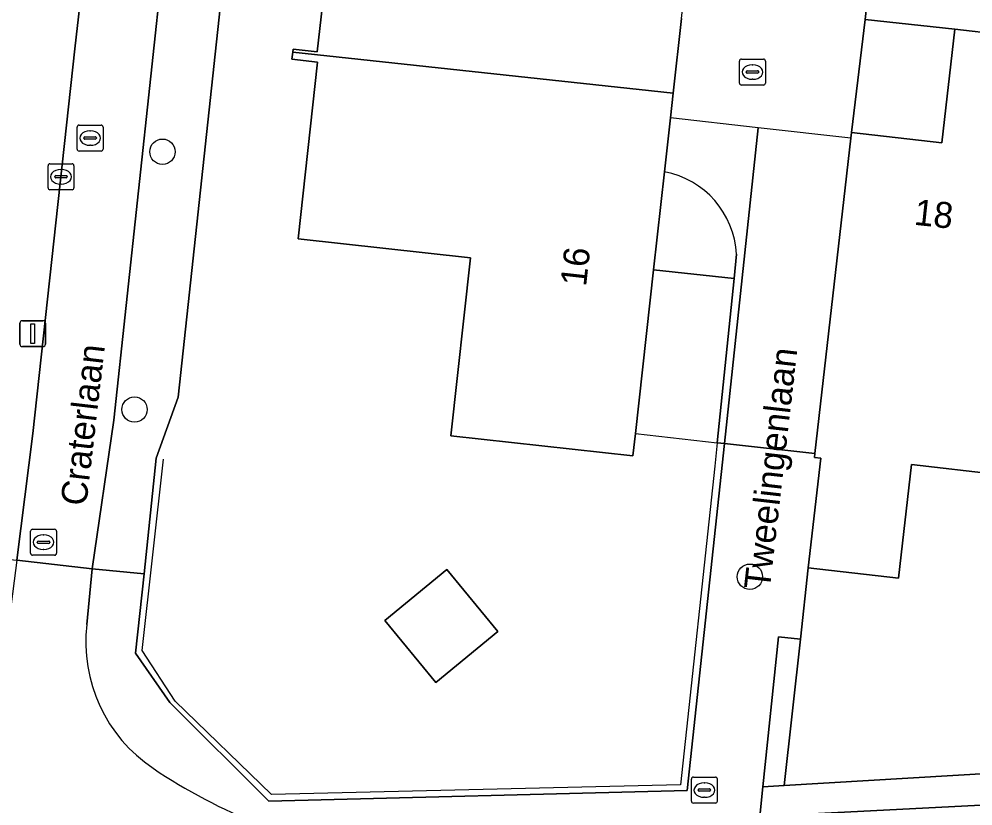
# Model space of a CAD drawing. Extents: x 162396 to 163643, y 386452 to 387406.
# Drawn here: x 162646 to 162682.82, y 386467.41 to 386497.76 of the extents above; entities that cross this region are included whole.
import ezdxf

# ---------------------------------------------------------------- set-up
doc = ezdxf.new("R2010")
doc.units = 0
for name, color, linetype in [('IMGEO_Berm_groen', 7, 'Continuous'), ('IMGEO_Boom', 7, 'Continuous'), ('IMGEO_Erf', 7, 'Continuous'), ('IMGEO_Fietspad_gesloten', 7, 'Continuous'), ('IMGEO_Fietspad_open', 7, 'Continuous'), ('IMGEO_Groenvoorziening', 7, 'Continuous'), ('IMGEO_Kolk', 7, 'Continuous'), ('IMGEO_Lichtmast', 7, 'Continuous'), ('IMGEO_Muur', 7, 'Continuous'), ('IMGEO_Openbare_ruimte_label', 7, 'Continuous'), ('IMGEO_Pand', 7, 'Continuous'), ('IMGEO_Pand_nummerreeks', 7, 'Continuous'), ('IMGEO_Pand_overbouw', 7, 'Continuous'), ('IMGEO_Rijbaan_lokaal_open', 7, 'Continuous'), ('IMGEO_Rioolput', 7, 'Continuous'), ('IMGEO_Voetpad_open', 7, 'Continuous')]:
    doc.layers.add(name, color=color, linetype=linetype)

msp = doc.modelspace()

# ---------------------------------------------------------------- linework, layer by layer
at = {"layer": 'IMGEO_Berm_groen'}
msp.add_lwpolyline([(162685.297, 386468.773), (162675.534, 386468.191), (162674.712, 386468.15), (162674.593, 386466.997), (162685.391, 386467.551)], close=True, dxfattribs=at)
at = {"layer": 'IMGEO_Boom'}
for centre in [(162651.534, 386492.646), (162650.454, 386482.699), (162674.209, 386476.249)]:
    msp.add_circle(centre, 0.489, dxfattribs=at)
at = {"layer": 'IMGEO_Erf'}
for points in [[(162653.954, 386500), (162652.14, 386483.177), (162651.294, 386480.824), (162650.821, 386476.366), (162650.496, 386473.305), (162651.817, 386471.397), (162655.639, 386467.593), (162671.786, 386468.002), (162673.225, 386481.39), (162672.948, 386481.421), (162673.598, 386487.762), (162670.493, 386488.084), (162669.791, 386481.774), (162669.695, 386480.909), (162662.664, 386481.69), (162663.427, 386488.55), (162656.767, 386489.29), (162657.524, 386496.103), (162656.532, 386496.213), (162656.562, 386496.484), (162656.576, 386496.61), (162657.511, 386496.506), (162657.899, 386500)], [(162708.804, 386484.322), (162705.271, 386484.727), (162702.148, 386485.085), (162701.66, 386480.83), (162698.283, 386481.217), (162697.979, 386478.568), (162697.474, 386478.626), (162690.7, 386479.402), (162683.78, 386480.194), (162680.447, 386480.576), (162679.946, 386476.199), (162676.46, 386476.598), (162676.157, 386473.844), (162675.534, 386468.191), (162685.297, 386468.773), (162686.376, 386468.838), (162699.459, 386469.63), (162700.524, 386469.694), (162706.572, 386470.062), (162707.634, 386470.126), (162713.9, 386470.497), (162714.941, 386470.557), (162732.655, 386471.574)]]:
    msp.add_lwpolyline(points, dxfattribs=at)
for points in [[(162678.137, 386493.391), (162681.623, 386492.992), (162682.125, 386497.376), (162678.661, 386497.746)], [(162662.512, 386476.528), (162664.477, 386474.131), (162662.08, 386472.165), (162660.114, 386474.563)]]:
    msp.add_lwpolyline(points, close=True, dxfattribs=at)
at = {"layer": 'IMGEO_Fietspad_gesloten'}
for points in [[(162648.608, 386474.401), (162648.825, 386476.553), (162645.908, 386476.892), (162645.639, 386474.787)], [(162745.417, 386471.64), (162744.381, 386471.562), (162715.01, 386469.312), (162713.97, 386469.239), (162707.758, 386468.81), (162706.663, 386468.77), (162700.617, 386468.394), (162699.554, 386468.328), (162686.477, 386467.606), (162685.391, 386467.551), (162674.593, 386466.997), (162655.671, 386466.609), (162655.276, 386466.693)]]:
    msp.add_lwpolyline(points, dxfattribs=at)
for centre, radius, start, end in [((162654.434, 386473.733), 5.864, 173.4629, 236.1556), ((162663.327, 386486.908), 21.759, 236.0268, 248.2838)]:
    msp.add_arc(centre, radius, start, end, dxfattribs=at)
at = {"layer": 'IMGEO_Fietspad_open'}
msp.add_lwpolyline([(162645.908, 386476.892), (162648.825, 386476.553), (162649.657, 386482.292), (162651.56, 386500), (162655.899, 386540.406), (162655.811, 386540.036), (162655.55, 386539.18), (162655.214, 386538.352), (162654.805, 386537.557), (162654.327, 386536.802), (162653.783, 386536.092), (162652.314, 386534.776), (162651.092, 386522.672), (162648.531, 386500), (162648.149, 386496.622), (162646.532, 386481.777)], close=True, dxfattribs=at)
at = {"layer": 'IMGEO_Groenvoorziening'}
msp.add_lwpolyline([(162676.157, 386473.844), (162675.31, 386473.932), (162674.712, 386468.15), (162675.534, 386468.191)], close=True, dxfattribs=at)
at = {"layer": 'IMGEO_Kolk'}
for p, q in [((162673.807, 386495.295), (162673.807, 386496.147)), ((162673.882, 386496.221), (162674.734, 386496.221)), ((162674.295, 386496.001), (162674.32, 386496.001)), ((162674.808, 386496.147), (162674.808, 386495.295)), ((162674.066, 386495.715), (162674.066, 386495.727)), ((162674.504, 386495.678), (162674.106, 386495.678)), ((162674.109, 386495.764), (162674.507, 386495.764)), ((162674.55, 386495.727), (162674.55, 386495.715)), ((162674.734, 386495.221), (162673.882, 386495.221)), ((162674.318, 386495.441), (162674.293, 386495.441)), ((162647.116, 386491.255), (162647.116, 386492.107)), ((162647.191, 386492.181), (162648.043, 386492.181)), ((162647.604, 386491.961), (162647.629, 386491.961)), ((162648.117, 386492.107), (162648.117, 386491.255)), ((162647.375, 386491.675), (162647.375, 386491.687)), ((162647.813, 386491.638), (162647.415, 386491.638)), ((162647.418, 386491.724), (162647.816, 386491.724)), ((162647.859, 386491.687), (162647.859, 386491.675)), ((162648.043, 386491.181), (162647.191, 386491.181)), ((162647.627, 386491.401), (162647.602, 386491.401))]:
    msp.add_line(p, q, dxfattribs=at)
for points in [[(162673.807, 386495.295), (162673.807, 386496.147)], [(162673.882, 386496.221), (162674.734, 386496.221)], [(162674.808, 386496.147), (162674.808, 386495.295)], [(162674.734, 386495.221), (162673.882, 386495.221)], [(162647.116, 386491.255), (162647.116, 386492.107)], [(162647.191, 386492.181), (162648.043, 386492.181)], [(162648.117, 386492.107), (162648.117, 386491.255)], [(162648.043, 386491.181), (162647.191, 386491.181)]]:
    msp.add_lwpolyline(points, dxfattribs=at)
for centre, radius, start, end in [((162673.884, 386496.145), 0.0765, 91.552, 178.448), ((162673.884, 386496.145), 0.0765, 91.552, 178.448), ((162674.732, 386496.145), 0.0765, 1.552, 88.448), ((162674.732, 386496.145), 0.0765, 1.552, 88.448), ((162674.106, 386495.724), 0.0403, 85.8775, 175.7526), ((162674.103, 386495.714), 0.0366, 178.938, 274.7102), ((162674.507, 386495.721), 0.043, 264.8664, 352.4533), ((162674.511, 386495.726), 0.0386, 1.7309, 96.639), ((162673.884, 386495.297), 0.0765, 181.552, 268.448), ((162673.884, 386495.297), 0.0765, 181.552, 268.448), ((162674.732, 386495.297), 0.0765, 271.552, 358.448), ((162674.732, 386495.297), 0.0765, 271.552, 358.448), ((162647.193, 386492.105), 0.0765, 91.552, 178.448), ((162647.193, 386492.105), 0.0765, 91.552, 178.448), ((162648.041, 386492.105), 0.0765, 1.552, 88.448), ((162648.041, 386492.105), 0.0765, 1.552, 88.448), ((162647.415, 386491.684), 0.0403, 85.8775, 175.7526), ((162647.412, 386491.674), 0.0366, 178.938, 274.7102), ((162647.816, 386491.681), 0.043, 264.8664, 352.4533), ((162647.82, 386491.686), 0.0386, 1.7309, 96.639), ((162647.193, 386491.257), 0.0765, 181.552, 268.448), ((162647.193, 386491.257), 0.0765, 181.552, 268.448), ((162648.041, 386491.257), 0.0765, 271.552, 358.448), ((162648.041, 386491.257), 0.0765, 271.552, 358.448)]:
    msp.add_arc(centre, radius, start, end, dxfattribs=at)
for centre, major_axis, ratio, start_param, end_param in [((162674.294, 386495.721), (-0.387, 0.002), 0.722429, 4.712389, 7.853982), ((162674.319, 386495.721), (-0.39, 0.002), 0.717154, 1.570796, 4.712389), ((162647.603, 386491.681), (-0.387, 0.002), 0.722429, 4.712389, 7.853982), ((162647.628, 386491.681), (-0.39, 0.002), 0.717154, 1.570796, 4.712389)]:
    msp.add_ellipse(centre, major_axis=major_axis, ratio=ratio, start_param=start_param, end_param=end_param, dxfattribs=at)
at = {"layer": 'IMGEO_Lichtmast'}
for p, q in [((162646.028, 386485.228), (162646.028, 386486.028)), ((162646.028, 386486.028), (162646.028, 386485.228)), ((162646.128, 386486.128), (162646.918, 386486.128)), ((162646.918, 386486.128), (162646.128, 386486.128)), ((162647.018, 386486.028), (162647.018, 386485.228)), ((162647.018, 386485.228), (162647.018, 386486.028)), ((162646.918, 386485.128), (162646.128, 386485.128)), ((162646.128, 386485.128), (162646.918, 386485.128))]:
    msp.add_line(p, q, dxfattribs=at)
msp.add_lwpolyline([(162646.448, 386486.003), (162646.598, 386486.003), (162646.598, 386485.253), (162646.448, 386485.253), (162646.448, 386486.003)], dxfattribs=at)
for centre, start, end in [((162646.128, 386486.028), 90, 180), ((162646.128, 386486.028), 90, 180), ((162646.918, 386486.028), 0, 90), ((162646.918, 386486.028), 360, 90), ((162646.128, 386485.228), 180, 270), ((162646.128, 386485.228), 180, 270), ((162646.918, 386485.228), 270, 0), ((162646.918, 386485.228), 270, 0)]:
    msp.add_arc(centre, 0.1, start, end, dxfattribs=at)
at = {"layer": 'IMGEO_Muur'}
for points in [[(162672.948, 386481.421), (162672.85, 386480.517)], [(162672.85, 386480.517), (162671.524, 386468.223), (162655.736, 386467.848), (162652.022, 386471.451), (162650.749, 386473.407), (162651.57, 386480.789)], [(162676.157, 386473.844), (162676.46, 386476.598)], [(162685.297, 386468.773), (162675.534, 386468.191), (162676.157, 386473.844)]]:
    msp.add_lwpolyline(points, dxfattribs=at)
at = {"layer": 'IMGEO_Pand'}
for points in [[(162671.817, 386500), (162672.462, 386505.808), (162672.793, 386508.782), (162665.724, 386509.568), (162664.964, 386502.729), (162658.285, 386503.471), (162657.899, 386500), (162657.511, 386496.506), (162656.576, 386496.61), (162656.562, 386496.484), (162671.251, 386494.908), (162671.571, 386497.786)], [(162676.46, 386476.598), (162679.946, 386476.199), (162680.447, 386480.576), (162683.78, 386480.194), (162685.702, 386496.966), (162682.125, 386497.376), (162681.623, 386492.992), (162678.137, 386493.391), (162678.111, 386493.167), (162676.718, 386481), (162676.701, 386480.849), (162676.944, 386480.821)], [(162670.914, 386491.872), (162671.145, 386493.953), (162671.251, 386494.908), (162656.562, 386496.484), (162656.532, 386496.213), (162657.524, 386496.103), (162656.767, 386489.29), (162663.427, 386488.55), (162662.664, 386481.69), (162669.695, 386480.909), (162669.791, 386481.774), (162670.493, 386488.084)], [(162662.512, 386476.528), (162660.114, 386474.563), (162662.08, 386472.165), (162664.477, 386474.131)]]:
    msp.add_lwpolyline(points, close=True, dxfattribs=at)
at = {"layer": 'IMGEO_Pand_overbouw'}
for points in [[(162674.534, 386493.571), (162671.145, 386493.953), (162670.914, 386491.872), (162670.493, 386488.084), (162669.791, 386481.774), (162672.948, 386481.421), (162673.225, 386481.39)], [(162674.534, 386493.571), (162673.225, 386481.39), (162676.718, 386481), (162678.111, 386493.167)]]:
    msp.add_lwpolyline(points, close=True, dxfattribs=at)
at = {"layer": 'IMGEO_Rijbaan_lokaal_open'}
for points in [[(162694.231, 386503.125), (162693.199, 386503.277), (162686.483, 386504.043), (162679.454, 386504.83), (162678.661, 386497.746), (162682.125, 386497.376), (162685.702, 386496.966), (162689.278, 386496.557), (162695.978, 386495.954), (162699.359, 386495.567), (162699.661, 386498.206), (162703.573, 386497.758), (162706.733, 386497.396), (162713.711, 386496.597), (162714.057, 386500), (162714.825, 386507.563)], [(162673.689, 386488.692), (162673.598, 386487.762), (162672.948, 386481.421), (162673.225, 386481.39), (162676.718, 386481), (162678.111, 386493.167), (162678.137, 386493.391), (162678.661, 386497.746), (162679.454, 386504.83)], [(162671.571, 386497.786), (162671.251, 386494.908), (162671.145, 386493.953), (162670.914, 386491.872)]]:
    msp.add_lwpolyline(points, dxfattribs=at)
msp.add_arc((162670.277, 386488.515), 3.417, 2.9638, 79.2548, dxfattribs=at)
at = {"layer": 'IMGEO_Rioolput'}
for p, q in [((162648.238, 386492.748), (162648.238, 386493.6)), ((162648.313, 386493.674), (162649.165, 386493.674)), ((162648.726, 386493.454), (162648.751, 386493.454)), ((162649.239, 386493.6), (162649.239, 386492.748)), ((162648.497, 386493.168), (162648.497, 386493.18)), ((162648.935, 386493.131), (162648.537, 386493.131)), ((162648.54, 386493.217), (162648.938, 386493.217)), ((162648.981, 386493.18), (162648.981, 386493.168)), ((162649.165, 386492.674), (162648.313, 386492.674)), ((162648.749, 386492.894), (162648.724, 386492.894)), ((162646.442, 386477.155), (162646.442, 386478.007)), ((162646.517, 386478.081), (162647.369, 386478.081)), ((162647.443, 386478.007), (162647.443, 386477.155)), ((162646.701, 386477.575), (162646.701, 386477.587)), ((162647.139, 386477.538), (162646.741, 386477.538)), ((162646.744, 386477.624), (162647.142, 386477.624)), ((162646.93, 386477.861), (162646.955, 386477.861)), ((162647.185, 386477.587), (162647.185, 386477.575)), ((162646.953, 386477.301), (162646.928, 386477.301)), ((162647.369, 386477.081), (162646.517, 386477.081)), ((162671.951, 386467.593), (162671.951, 386468.445)), ((162672.026, 386468.519), (162672.878, 386468.519)), ((162672.952, 386468.445), (162672.952, 386467.593)), ((162672.21, 386468.013), (162672.21, 386468.025)), ((162672.648, 386467.976), (162672.25, 386467.976)), ((162672.253, 386468.062), (162672.651, 386468.062)), ((162672.439, 386468.299), (162672.464, 386468.299)), ((162672.694, 386468.025), (162672.694, 386468.013)), ((162672.462, 386467.739), (162672.437, 386467.739)), ((162672.878, 386467.519), (162672.026, 386467.519))]:
    msp.add_line(p, q, dxfattribs=at)
for points in [[(162648.238, 386492.748), (162648.238, 386493.6)], [(162648.313, 386493.674), (162649.165, 386493.674)], [(162649.239, 386493.6), (162649.239, 386492.748)], [(162649.165, 386492.674), (162648.313, 386492.674)], [(162646.442, 386477.155), (162646.442, 386478.007)], [(162646.517, 386478.081), (162647.369, 386478.081)], [(162647.443, 386478.007), (162647.443, 386477.155)], [(162647.369, 386477.081), (162646.517, 386477.081)], [(162671.951, 386467.593), (162671.951, 386468.445)], [(162672.026, 386468.519), (162672.878, 386468.519)], [(162672.952, 386468.445), (162672.952, 386467.593)], [(162672.878, 386467.519), (162672.026, 386467.519)]]:
    msp.add_lwpolyline(points, dxfattribs=at)
for centre, radius, start, end in [((162648.315, 386493.598), 0.0765, 91.552, 178.448), ((162648.315, 386493.598), 0.0765, 91.552, 178.448), ((162649.163, 386493.598), 0.0765, 1.552, 88.448), ((162649.163, 386493.598), 0.0765, 1.552, 88.448), ((162648.537, 386493.177), 0.0403, 85.8775, 175.7526), ((162648.534, 386493.167), 0.0366, 178.938, 274.7102), ((162648.938, 386493.174), 0.043, 264.8664, 352.4533), ((162648.942, 386493.179), 0.0386, 1.7309, 96.639), ((162648.315, 386492.75), 0.0765, 181.552, 268.448), ((162648.315, 386492.75), 0.0765, 181.552, 268.448), ((162649.163, 386492.75), 0.0765, 271.552, 358.448), ((162649.163, 386492.75), 0.0765, 271.552, 358.448), ((162646.519, 386478.005), 0.0765, 91.552, 178.448), ((162646.519, 386478.005), 0.0765, 91.552, 178.448), ((162647.367, 386478.005), 0.0765, 1.552, 88.448), ((162647.367, 386478.005), 0.0765, 1.552, 88.448), ((162646.741, 386477.584), 0.0403, 85.8775, 175.7526), ((162646.738, 386477.574), 0.0366, 178.938, 274.7102), ((162647.142, 386477.581), 0.043, 264.8664, 352.4533), ((162647.146, 386477.586), 0.0386, 1.7309, 96.639), ((162646.519, 386477.157), 0.0765, 181.552, 268.448), ((162646.519, 386477.157), 0.0765, 181.552, 268.448), ((162647.367, 386477.157), 0.0765, 271.552, 358.448), ((162647.367, 386477.157), 0.0765, 271.552, 358.448), ((162672.028, 386468.443), 0.0765, 91.552, 178.448), ((162672.028, 386468.443), 0.0765, 91.552, 178.448), ((162672.876, 386468.443), 0.0765, 1.552, 88.448), ((162672.876, 386468.443), 0.0765, 1.552, 88.448), ((162672.25, 386468.022), 0.0403, 85.8775, 175.7526), ((162672.247, 386468.012), 0.0366, 178.938, 274.7102), ((162672.651, 386468.019), 0.043, 264.8664, 352.4533), ((162672.655, 386468.024), 0.0386, 1.7309, 96.639), ((162672.028, 386467.595), 0.0765, 181.552, 268.448), ((162672.028, 386467.595), 0.0765, 181.552, 268.448), ((162672.876, 386467.595), 0.0765, 271.552, 358.448), ((162672.876, 386467.595), 0.0765, 271.552, 358.448)]:
    msp.add_arc(centre, radius, start, end, dxfattribs=at)
for centre, major_axis, ratio, start_param, end_param in [((162648.725, 386493.174), (-0.387, 0.002), 0.722429, 4.712389, 7.853982), ((162648.75, 386493.174), (-0.39, 0.002), 0.717154, 1.570796, 4.712389), ((162646.929, 386477.581), (-0.387, 0.002), 0.722429, 4.712389, 7.853982), ((162646.954, 386477.581), (-0.39, 0.002), 0.717154, 1.570796, 4.712389), ((162672.438, 386468.019), (-0.387, 0.002), 0.722429, 4.712389, 7.853982), ((162672.463, 386468.019), (-0.39, 0.002), 0.717154, 1.570796, 4.712389)]:
    msp.add_ellipse(centre, major_axis=major_axis, ratio=ratio, start_param=start_param, end_param=end_param, dxfattribs=at)
at = {"layer": 'IMGEO_Voetpad_open'}
for points in [[(162657.295, 386553.409), (162655.899, 386540.406), (162651.56, 386500), (162649.657, 386482.292), (162648.825, 386476.553), (162650.821, 386476.366), (162651.294, 386480.824), (162652.14, 386483.177), (162653.954, 386500), (162659.642, 386552.743), (162659.646, 386552.885), (162660.142, 386557.933)], [(162670.914, 386491.872), (162670.493, 386488.084), (162673.598, 386487.762), (162673.689, 386488.692)], [(162676.46, 386476.598), (162676.944, 386480.821), (162676.701, 386480.849), (162676.718, 386481), (162673.225, 386481.39), (162671.786, 386468.002), (162655.639, 386467.593), (162651.817, 386471.397), (162650.496, 386473.305), (162650.821, 386476.366), (162648.825, 386476.553), (162648.608, 386474.401)], [(162655.276, 386466.693), (162655.671, 386466.609), (162674.593, 386466.997), (162674.712, 386468.15), (162675.31, 386473.932), (162676.157, 386473.844), (162676.46, 386476.598)]]:
    msp.add_lwpolyline(points, dxfattribs=at)
msp.add_lwpolyline([(162652.314, 386534.776), (162652.171, 386534.67), (162651.301, 386534.093), (162650.383, 386533.596), (162649.424, 386533.182), (162649.066, 386533.064), (162647.893, 386522.448), (162647.88, 386522.248), (162645.441, 386500), (162642.901, 386477.877), (162642.817, 386477.198), (162645.908, 386476.892), (162646.532, 386481.777), (162648.149, 386496.622), (162648.531, 386500), (162651.092, 386522.672)], close=True, dxfattribs=at)
for centre, radius, start, end in [((162670.277, 386488.515), 3.417, 2.9638, 79.2548), ((162654.434, 386473.733), 5.864, 173.4629, 236.1556), ((162663.327, 386486.908), 21.759, 236.0268, 248.2838)]:
    msp.add_arc(centre, radius, start, end, dxfattribs=at)

# ---------------------------------------------------------------- texts
at = {"layer": 'IMGEO_Openbare_ruimte_label'}
for s, rotation, p in [('Craterlaan', 83.337, (162648.589, 386478.953)), ('Tweelingenlaan', 83.4574, (162674.974, 386475.717))]:
    msp.add_text(s, height=1, rotation=rotation, dxfattribs=at).set_placement(p)
at = {"layer": 'IMGEO_Pand_nummerreeks'}
for s, rotation, p in [('18', 353.7891, (162680.518, 386489.833)), ('16', 83.6598, (162667.884, 386487.425))]:
    msp.add_text(s, height=1, rotation=rotation, dxfattribs=at).set_placement(p)

doc.saveas('drawing.dxf')
